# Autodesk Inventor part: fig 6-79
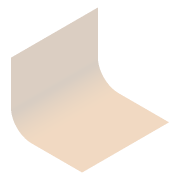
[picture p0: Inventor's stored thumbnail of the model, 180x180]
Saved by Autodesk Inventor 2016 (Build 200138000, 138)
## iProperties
Shininess: 64.0
Length Units: 11269
Angle Units: 11279
Time Units: 11290
Mass Units: 11283
Length Display Precision: 3
Angle Display Precision: 2
Compacted: True
Part Number: fig 6-79
Document SubType Name: Modeling
Created: 2003-10
Designer: Owner
Manufacturer: Standard
Standards Organization: Custom
Density: 1 g/cm^3
Material: Generic
Appearance: Default
Density: 0.0
Volumn: 0.0
Area: 0.0
PropertySet Name: Model Information
Control State: 0
Master: False
Checked Out: False
Author: Owner
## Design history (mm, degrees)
node "Sketch1"
sketch "Sketch2"
  geometry: L1 (22.777, 31.862)-(22.777, 0.2); L2 (7.777, -14.8)-(-29.161, -14.8); A1 r 15 centre (7.777, 0.2) between (7.777, -14.8) and (22.777, 0.2)
  constraints: 4 end point, 2 point on circle, 2 tangent, 1 centre point, 1 perpendicular, 1 vertical
  dimensions: "d23" = 15 radius of A1
extrude_surface "ExtrusionSrf1" sketch "Sketch2" dims "d24" = 63.5, "d25" = 0
body "Srf1"
